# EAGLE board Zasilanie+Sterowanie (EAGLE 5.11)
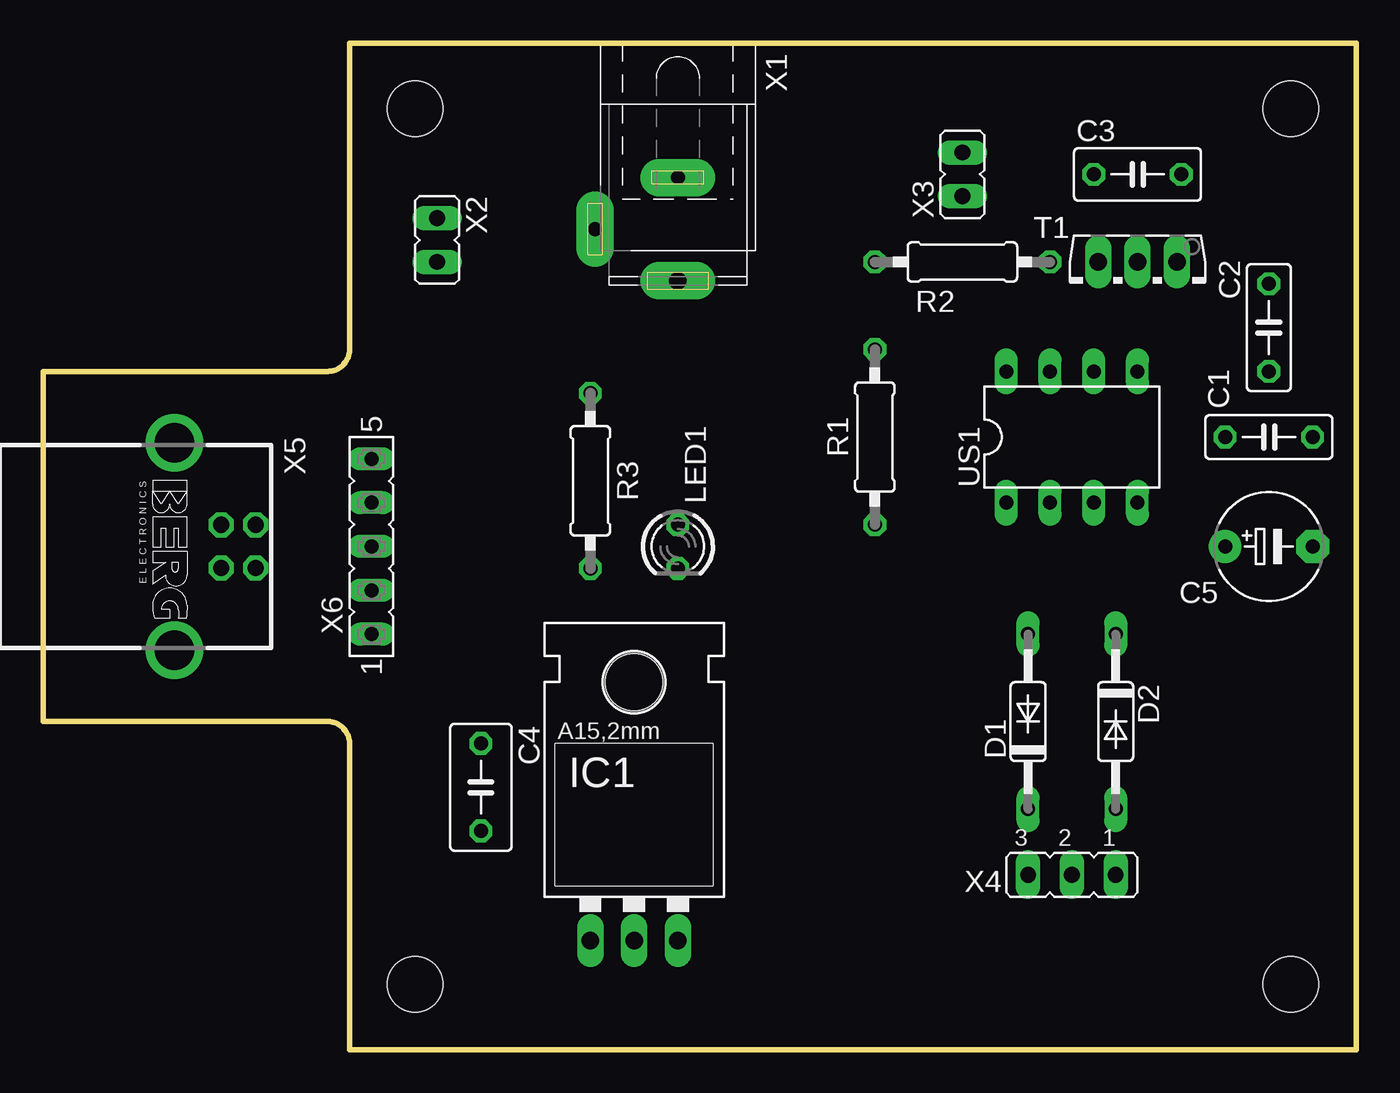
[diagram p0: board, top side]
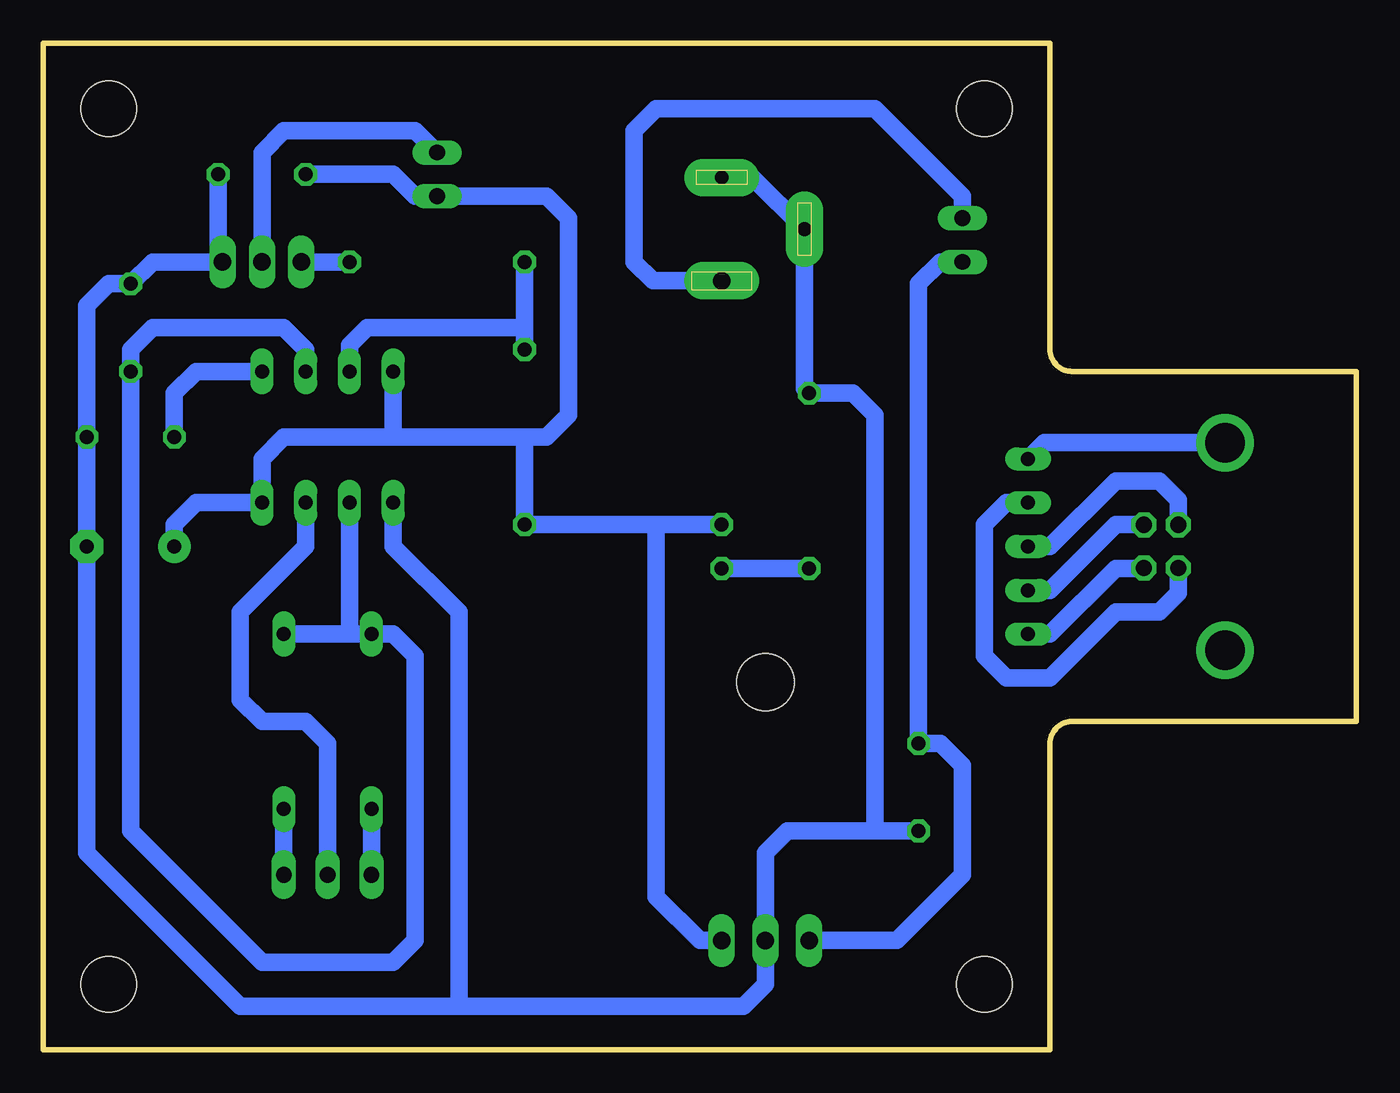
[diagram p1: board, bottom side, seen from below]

Size 76.2 x 58.42 mm. Coordinates in mm from the lower left corner, seen from the top.
Outline: 17.78,58.42 76.2,58.42 76.2,0 17.78,0 17.78,17.78 arc90 16.51,19.05 0,19.05 0,39.37 16.51,39.37 arc90 17.78,40.64 17.78,58.42
Copper layers (1*16): Top 0.035mm / dielectric 1.5mm / Bottom 0.035mm
Design rules "default": minimum track width 10mil, minimum drill 24mil, track to track 8mil, track to pad 8mil, pad to pad 8mil, via to via 8mil, smd to smd 8mil, copper to edge 40mil, drill to drill 8mil, minimum pad ring 10mil, minimum via ring 8mil, stop-mask expansion 4mil, vias tented up to drill 0mil, thermal gap 10mil
Holes 3.2 mm at 72.39,54.61 72.39,3.81 21.59,54.61 21.59,3.81

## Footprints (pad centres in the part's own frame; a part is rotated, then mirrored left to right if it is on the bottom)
C050-025X075 = drill 0.813 octagon: 1 -2.54,0; 2 2.54,0
C050-030X075 = drill 0.813 octagon: 1 -2.54,0; 2 2.54,0
C050-035X075 = drill 0.813 octagon: 1 -2.54,0; 2 2.54,0
E5-6 = drill 0.813 pad 1.905 round: + -2.54,0 | drill 0.813 pad 1.905 octagon: - 2.54,0
DO35-10 = drill 0.813 long: A 5.08,0; C -5.08,0
78XXL = drill 1.016 long: GND 0,-3.81; IN -2.54,-3.81; OUT 2.54,-3.81 | hole 3.302: 0,11.176
LED3MM = drill 0.813 octagon: A -1.27,0; K 1.27,0
0207/10 = drill 0.813 octagon: 1 -5.08,0; 2 5.08,0
TO126AV = drill 1.016 long: B 2.286,-1.27; C 0,-1.27; E -2.286,-1.27
DIL08 = drill 0.813 long: 1 -3.81,-3.81; 2 -1.27,-3.81; 3 1.27,-3.81; 4 3.81,-3.81; 5 3.81,3.81; 6 1.27,3.81; 7 -1.27,3.81; 8 -3.81,3.81
SPC4078 = drill 0.8 pad 2.184 long: 1 -3,0; 2 0,-4.8 | drill 1 pad 2.184 long: 3 3,0
JP1 = drill 0.914 long: 1 0,-1.27; 2 0,1.27
JP2 = drill 0.914 long: 1 -2.54,0; 2 0,0; 3 2.54,0
PN61729-S = drill 0.95 octagon: 1 1.25,4.71; 2 -1.25,4.71; 3 -1.25,2.71; 4 1.25,2.71 | drill 2.3 pad 2.9 round: S1 -6.02,0; S2 6.02,0
FE05-1 = drill 0.813 long: 1 -5.08,0; 2 -2.54,0; 3 0,0; 4 2.54,0; 5 5.08,0

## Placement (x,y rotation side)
C1  10nF  [C050-025X075]  71.12,35.56 0 top
C2  100nF  [C050-025X075]  71.12,41.91 90 top
C3  100nF  [C050-030X075]  63.5,50.8 0 top
C4  220n  [C050-035X075]  25.4,15.24 270 top
C5  100uF  [E5-6]  71.12,29.21 0 top
D1  1N4148  [DO35-10]  57.15,19.05 90 top
D2  1N4148  [DO35-10]  62.23,19.05 270 top
IC1  7809  [78XXL]  34.29,10.16 0 top
LED1  Y  [LED3MM]  36.83,29.21 270 top
R1  10k  [0207/10]  48.26,35.56 90 top
R2  1k  [0207/10]  53.34,45.72 0 top
R3  470  [0207/10]  31.75,33.02 270 top
T1  BD139  [TO126AV]  63.5,44.45 180 top
US1  NE555N  [DIL08]  59.69,35.56 0 top
X1  11-18V  [SPC4078]  36.83,47.62 270 top
X2  ON/OFF  [JP1]  22.86,46.99 180 top
X3  LED_W  [JP1]  53.34,50.8 0 top
X4  POT_10k  [JP2]  59.69,10.16 180 top
X5  USB_B  [PN61729-S]  7.62,29.21 270 top
X6  DB9  [FE05-1]  19.05,29.21 90 top

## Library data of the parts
C1-C5 R1-R3 = rcl
D1 D2 = diode
IC1 = v-reg
LED1 = led
T1 = transistor-power
US1 = linear
X1 = con-jack; OC_FARNELL: unknown; OC_NEWARK: unknown
X2-X4 = jumper
X5 = con-berg; OC_FARNELL: unknown; OC_NEWARK: unknown
X6 = con-lsta; OC_FARNELL: unknown; OC_NEWARK: unknown

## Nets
+ZAS: X5.1 X6.1
-ZAS: X5.4 X6.4
D+: X5.3 X6.3
D-: X5.2 X6.2
GND: C1.2 C2.2 C3.2 C4.2 C5.- IC1.GND R3.1 T1.E US1.1 X1.1 X1.2
N$1: C1.1 US1.5
N$2: C4.1 IC1.IN X2.2
N$3: T1.C X3.2
N$4: C2.1 D1.A D2.C US1.2 US1.6
N$5: D1.C X4.3
N$6: D2.A X4.1
N$7: US1.3 X4.2
N$8: R1.2 R2.1 US1.7
N$9: R2.2 T1.B
N$11: LED1.K R3.2
N$12: X1.3 X2.1
SHIELD: X5.S1 X6.5
V+: C3.1 C5.+ IC1.OUT LED1.A R1.1 US1.4 US1.8 X3.1

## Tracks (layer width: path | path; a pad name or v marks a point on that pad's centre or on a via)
+ZAS
  Bottom 1.016: X6.1 17.78,24.13 13.97,27.94 12.35,27.94 X5.1
-ZAS
  Bottom 1.016: X6.4 20.32,31.75 21.59,30.48 21.59,22.86 20.32,21.59 17.78,21.59 13.97,25.4 11.43,25.4 10.33,26.5 X5.4
D+
  Bottom 1.016: X6.3 17.78,29.21 13.97,33.02 11.43,33.02 10.33,31.92 X5.3
D-
  Bottom 1.016: X6.2 17.78,26.67 13.97,30.48 12.35,30.48 X5.2
GND
  Bottom 1.016: 52.07,2.54 64.77,2.54 73.66,11.43 C5.- C1.2 73.66,43.18 72.39,44.45 C2.2 69.85,45.72 66.04,45.72 | 52.07,2.54 52.07,25.4 55.88,29.21 US1.1 | 52.07,2.54 35.56,2.54 34.29,3.81 IC1.GND 34.29,11.43 33.02,12.7 27.94,12.7 | 27.94,12.7 C4.2 | 27.94,12.7 27.94,36.83 29.21,38.1 R3.1 32.03,38.38 X1.2 35.03,50.62 X1.1 | 66.04,45.72 C3.2 | 66.04,45.72 T1.E
N$1
  Bottom 1.016: C1.1 68.58,38.1 67.31,39.37 US1.5
N$2
  Bottom 1.016: IC1.IN 26.67,6.35 22.86,10.16 22.86,16.51 24.13,17.78 C4.1 25.4,44.45 24.13,45.72 X2.2
N$3
  Bottom 1.016: T1.C 63.5,52.07 62.23,53.34 54.61,53.34 X3.2
N$4
  Bottom 1.016: 58.42,24.13 D1.A 55.88,24.13 54.61,22.86 54.61,6.35 55.88,5.08 63.5,5.08 71.12,12.7 C2.1 71.12,40.64 69.85,41.91 62.23,41.91 60.96,40.64 US1.6 | 58.42,24.13 D2.C | 58.42,24.13 US1.2
N$5
  Bottom 1.016: X4.3 D1.C
N$6
  Bottom 1.016: X4.1 D2.A
N$7
  Bottom 1.016: US1.3 60.96,29.21 64.77,25.4 64.77,20.32 63.5,19.05 60.96,19.05 59.69,17.78 X4.2
N$8
  Bottom 1.016: R1.2 48.26,41.91 | 48.26,41.91 57.4,41.91 58.42,40.89 US1.7 | 48.26,41.91 R2.1
N$9
  Bottom 1.016: R2.2 T1.B
N$11
  Bottom 1.016: R3.2 LED1.K
N$12
  Bottom 1.016: X2.1 22.86,49.53 27.94,54.61 40.64,54.61 41.91,53.34 41.91,45.72 40.81,44.62 X1.3
SHIELD
  Bottom 1.016: X5.S1 18.11,35.23 X6.5
V+
  Bottom 1.016: 55.88,35.56 US1.8 | 48.26,35.56 55.88,35.56 | 55.88,35.56 62.23,35.56 63.5,34.29 US1.4 67.31,31.75 68.58,30.48 C5.+ | 48.26,35.56 46.99,35.56 45.72,36.83 45.72,48.26 46.99,49.53 X3.1 54.61,49.53 55.88,50.8 C3.1 | 48.26,35.56 R1.1 40.64,30.48 | 40.64,30.48 LED1.A | IC1.OUT 38.1,6.35 40.64,8.89 40.64,30.48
